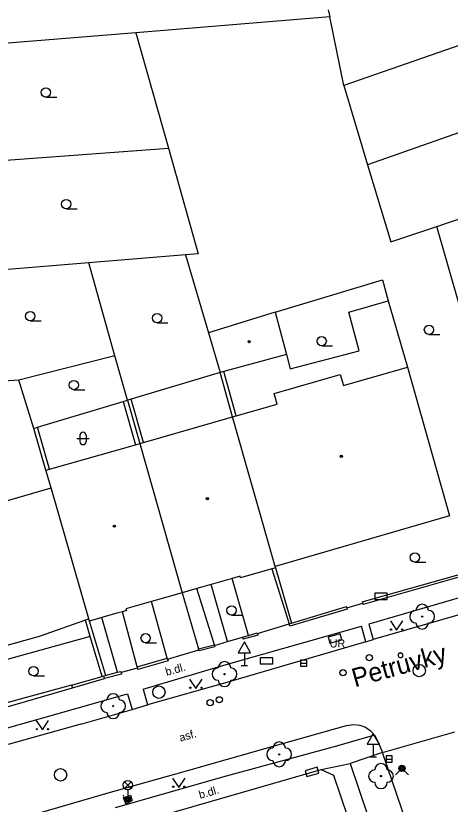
# Model space of a CAD drawing. Extents: x -596229 to -595156, y -1161237 to -1159376.
# Drawn here: x -596056.2 to -596021.2, y -1161042.3 to -1160978.8 of the extents above; entities that cross this region are included whole.
import ezdxf

# ---------------------------------------------------------------- set-up
doc = ezdxf.new("R2010")
doc.units = 0
for name, color, linetype in [('DOP - budovy nerozlisene - VP', 7, 'Continuous'), ('DOP - kresba z DSPS bez souradnic', 7, 'Continuous'), ('DOP - rozhrani ploch obecne', 7, 'Continuous'), ('Level 22', 7, 'Continuous'), ('Level 24', 7, 'Continuous'), ('Level 27', 7, 'Continuous'), ('Level 28', 7, 'Continuous'), ('Level 31', 7, 'Continuous'), ('Level 33', 7, 'Continuous'), ('Level 34', 7, 'Continuous'), ('Level 36', 7, 'Continuous'), ('Level 39', 7, 'Continuous'), ('Nazvy ulic', 7, 'Continuous'), ('Specificka linie pasportu komunikaci', 7, 'Continuous'), ('TM - budovy zdene_ betonove - VP', 7, 'Continuous'), ('TM - chodniky - VP', 7, 'Continuous'), ('TM - komunikace - VP', 7, 'Continuous'), ('TM - letecke snimky - pomocna linie', 7, 'Continuous'), ('TM - plot drateny_ kovovy - VP', 7, 'Continuous'), ('TM - plot dreveny - VP', 7, 'Continuous'), ('TM - plot zdeny_ ohradni zed - VP', 7, 'Continuous'), ('TM - podezdivka plotu - VP', 7, 'Continuous'), ('TM - popis objektu', 7, 'Continuous'), ('TM - popis povrchu', 7, 'Continuous'), ('TM - rozhrani mezi zpev. plochami mezi sebou - VP', 7, 'Continuous'), ('TM - rozhrani ploch obecne - VP', 7, 'Continuous'), ('TM - vjezd na pozemek', 7, 'Continuous')]:
    doc.layers.add(name, color=color, linetype=linetype)

msp = doc.modelspace()

# ---------------------------------------------------------------- linework, layer by layer
at = {"layer": 'DOP - budovy nerozlisene - VP'}
for points in [[(-596035.29, -1161002.69), (-596040.65, -1161004.33)], [(-596035.29, -1161002.69), (-596034.39, -1161006.09)], [(-596040.65, -1161004.33), (-596039.72, -1161007.54)], [(-596034.39, -1161006.09), (-596039.43, -1161007.46)], [(-596039.43, -1161007.46), (-596039.72, -1161007.54)]]:
    msp.add_lwpolyline(points, dxfattribs=at)
at = {"layer": 'DOP - kresba z DSPS bez souradnic'}
for points in [[(-596038.42, -1161011.03), (-596039.43, -1161007.46)], [(-596047.51, -1161009.87), (-596046.53, -1161013.34)], [(-596045.89, -1161013.16), (-596046.87, -1161009.68)], [(-596053.44, -1161015.32), (-596054.41, -1161011.94)]]:
    msp.add_lwpolyline(points, dxfattribs=at)
at = {"layer": 'DOP - rozhrani ploch obecne'}
for points in [[(-596006.38, -1160976.28), (-596029.78, -1160984.44)], [(-596031.02, -1160978.36), (-596030.9, -1160978.92)], [(-596030.9, -1160978.92), (-596046.51, -1160980.19)], [(-596029.78, -1160984.44), (-596030.9, -1160978.92)], [(-596046.51, -1160980.19), (-596062.76, -1160981.52)], [(-596046.51, -1160980.19), (-596043.88, -1160989.49)], [(-596004.21, -1160982.51), (-596027.86, -1160990.81)], [(-596029.78, -1160984.44), (-596027.86, -1160990.81)], [(-596062.05, -1160990.82), (-596043.88, -1160989.49)], [(-596043.88, -1160989.49), (-596041.48, -1160997.97)], [(-596022.3, -1160995.78), (-596006.25, -1160990.3)], [(-596027.86, -1160990.81), (-596025.98, -1160997.03)], [(-596025.98, -1160997.03), (-596022.3, -1160995.78)], [(-596042.5, -1160998.05), (-596050.27, -1160998.71)], [(-596041.48, -1160997.97), (-596042.5, -1160998.05)], [(-596042.5, -1160998.05), (-596040.65, -1161004.33)], [(-596050.27, -1160998.71), (-596061.38, -1160999.63)], [(-596048.18, -1161006.18), (-596050.27, -1160998.71)], [(-596035.29, -1161002.69), (-596026.67, -1161000.08)], [(-596026.67, -1161000.08), (-596026.19, -1161001.76)], [(-596026.19, -1161001.76), (-596024.65, -1161007.1)], [(-596048.18, -1161006.18), (-596055.9, -1161008.14)], [(-596047.16, -1161009.77), (-596048.18, -1161006.18)], [(-596039.72, -1161007.54), (-596046.87, -1161009.68)], [(-596038.71, -1161011.11), (-596039.72, -1161007.54)], [(-596055.9, -1161008.14), (-596060.7, -1161008.48)], [(-596054.7, -1161012.03), (-596055.9, -1161008.14)], [(-596054.41, -1161011.94), (-596047.51, -1161009.87)], [(-596047.51, -1161009.87), (-596047.16, -1161009.77)], [(-596046.87, -1161009.68), (-596047.16, -1161009.77)], [(-596047.16, -1161009.77), (-596046.18, -1161013.24)], [(-596054.7, -1161012.03), (-596054.41, -1161011.94)], [(-596053.73, -1161015.4), (-596054.7, -1161012.03)]]:
    msp.add_lwpolyline(points, dxfattribs=at)
at = {"layer": 'Level 22'}
for centre in [(-596023.47, -1161027.18), (-596039.37, -1161031.8), (-596048.32, -1161034.38), (-596034.97, -1161038.26), (-596026.78, -1161040.01)]:
    msp.add_circle(centre, 0.05, dxfattribs=at)
for centre, start, end in [((-596023.47, -1161026.68), 0, 180), ((-596023.97, -1161027.18), 90, 270), ((-596022.97, -1161027.18), 270, 90), ((-596023.47, -1161027.68), 180, 0), ((-596039.37, -1161031.3), 0, 180), ((-596039.87, -1161031.8), 90, 270), ((-596038.87, -1161031.8), 270, 90), ((-596039.37, -1161032.3), 180, 0), ((-596048.32, -1161033.88), 0, 180), ((-596048.82, -1161034.38), 90, 270), ((-596047.82, -1161034.38), 270, 90), ((-596048.32, -1161034.88), 180, 0), ((-596034.97, -1161037.76), 0, 180), ((-596035.47, -1161038.26), 90, 270), ((-596034.47, -1161038.26), 270, 90), ((-596034.97, -1161038.76), 180, 0), ((-596026.78, -1161039.51), 0, 180), ((-596027.28, -1161040.01), 90, 270), ((-596026.28, -1161040.01), 270, 90), ((-596026.78, -1161040.51), 180, 0)]:
    msp.add_arc(centre, 0.5, start, end, dxfattribs=at)
at = {"layer": 'Level 24'}
for points in [[(-596027.278, -1161025.799), (-596026.278, -1161025.799), (-596026.278, -1161025.299), (-596027.278, -1161025.299)], [(-596030.067, -1161028.563), (-596031.029, -1161028.836), (-596030.893, -1161029.317), (-596029.931, -1161029.044)], [(-596036.488, -1161030.989), (-596035.488, -1161030.989), (-596035.488, -1161030.489), (-596036.488, -1161030.489)], [(-596031.911, -1161039.296), (-596032.872, -1161039.574), (-596032.733, -1161040.055), (-596031.772, -1161039.777)]]:
    msp.add_lwpolyline(points, close=True, dxfattribs=at)
at = {"layer": 'Level 27'}
for p, q in [((-596033.24, -1161030.92), (-596032.74, -1161030.92)), ((-596026.37, -1161038.64), (-596025.87, -1161038.64))]:
    msp.add_line(p, q, dxfattribs=at)
for points in [[(-596033.24, -1161031.17), (-596032.74, -1161031.17), (-596032.74, -1161030.67), (-596033.24, -1161030.67)], [(-596026.37, -1161038.89), (-596025.87, -1161038.89), (-596025.87, -1161038.39), (-596026.37, -1161038.39)]]:
    msp.add_lwpolyline(points, close=True, dxfattribs=at)
for centre in [(-596023.7, -1161031.52), (-596044.64, -1161033.26), (-596052.55, -1161039.91)]:
    msp.add_circle(centre, 0.5, dxfattribs=at)
at = {"layer": 'Level 28'}
for centre in [(-596027.72, -1161030.48), (-596029.84, -1161031.68), (-596040.52, -1161034.11), (-596039.78, -1161033.87)]:
    msp.add_circle(centre, 0.25, dxfattribs=at)
at = {"layer": 'Level 31'}
msp.add_lwpolyline([(-596025.62, -1161039.92), (-596025.09, -1161039.39), (-596024.56, -1161039.92)], dxfattribs=at)
for radius in [0.25, 0.18, 0.11]:
    msp.add_circle((-596025.09, -1161039.39), radius, dxfattribs=at)
at = {"layer": 'Level 33'}
for p, q in [((-596047.415, -1161041), (-596046.885, -1161040.47)), ((-596047.415, -1161040.47), (-596046.885, -1161041)), ((-596047.15, -1161041.11), (-596047.15, -1161041.86))]:
    msp.add_line(p, q, dxfattribs=at)
for centre, radius in [((-596047.15, -1161040.735), 0.375), ((-596047.15, -1161041.86), 0.2), ((-596047.15, -1161041.86), 0.145), ((-596047.15, -1161041.86), 0.0876)]:
    msp.add_circle(centre, radius, dxfattribs=at)
at = {"layer": 'Level 34'}
for p, q in [((-596037.77, -1161030.082), (-596037.77, -1161031.1)), ((-596038.02, -1161031.1), (-596037.52, -1161031.1)), ((-596027.4, -1161037.442), (-596027.4, -1161038.46)), ((-596027.65, -1161038.46), (-596027.15, -1161038.46))]:
    msp.add_line(p, q, dxfattribs=at)
for points in [[(-596038.27, -1161030.082), (-596037.27, -1161030.082), (-596037.77, -1161029.216)], [(-596027.9, -1161037.442), (-596026.9, -1161037.442), (-596027.4, -1161036.576)]]:
    msp.add_lwpolyline(points, close=True, dxfattribs=at)
at = {"layer": 'Level 36'}
for p, q in [((-596053.73, -1160985.375), (-596052.855, -1160985.375)), ((-596052.1, -1160994.355), (-596051.225, -1160994.355)), ((-596054.99, -1161003.375), (-596054.115, -1161003.375)), ((-596044.79, -1161003.525), (-596043.915, -1161003.525)), ((-596022.92, -1161004.465), (-596022.045, -1161004.465)), ((-596031.55, -1161005.385), (-596030.675, -1161005.385)), ((-596051.48, -1161008.915), (-596050.605, -1161008.915)), ((-596051.246, -1161012.836), (-596050.246, -1161012.836)), ((-596050.996, -1161012.586), (-596050.996, -1161013.086)), ((-596050.496, -1161012.586), (-596050.496, -1161013.086)), ((-596024.05, -1161022.795), (-596023.175, -1161022.795)), ((-596038.8, -1161027.055), (-596037.925, -1161027.055)), ((-596045.71, -1161029.285), (-596044.835, -1161029.285)), ((-596054.72, -1161031.945), (-596053.845, -1161031.945))]:
    msp.add_line(p, q, dxfattribs=at)
for points in [[(-596026.02, -1161027.52), (-596025.52, -1161028.27), (-596025.02, -1161027.52)], [(-596042.17, -1161032.2), (-596041.67, -1161032.95), (-596041.17, -1161032.2)], [(-596054.51, -1161035.53), (-596054.01, -1161036.28), (-596053.51, -1161035.53)], [(-596043.54, -1161040.17), (-596043.04, -1161040.92), (-596042.54, -1161040.17)]]:
    msp.add_lwpolyline(points, dxfattribs=at)
for centre, radius in [((-596053.73, -1160985), 0.375), ((-596052.1, -1160993.98), 0.375), ((-596054.99, -1161003), 0.375), ((-596044.79, -1161003.15), 0.375), ((-596022.92, -1161004.09), 0.375), ((-596031.55, -1161005.01), 0.375), ((-596051.48, -1161008.54), 0.375), ((-596024.05, -1161022.42), 0.375), ((-596038.8, -1161026.68), 0.375), ((-596025.97, -1161028.22), 0.05), ((-596025.071, -1161028.22), 0.05), ((-596045.71, -1161028.91), 0.375), ((-596054.72, -1161031.57), 0.375), ((-596042.12, -1161032.9), 0.05), ((-596041.221, -1161032.9), 0.05), ((-596054.46, -1161036.23), 0.05), ((-596053.561, -1161036.23), 0.05), ((-596043.49, -1161040.87), 0.05), ((-596042.591, -1161040.87), 0.05)]:
    msp.add_circle(centre, radius, dxfattribs=at)
for centre, start, end in [((-596050.746, -1161012.586), 0, 180), ((-596050.746, -1161013.086), 180, 0)]:
    msp.add_arc(centre, 0.25, start, end, dxfattribs=at)
at = {"layer": 'Level 39'}
for centre, radius in [((-596037.38, -1161005.06), 0.09), ((-596037.38, -1161005.06), 0.0398), ((-596029.97, -1161014.28), 0.09), ((-596029.97, -1161014.28), 0.0398), ((-596040.74, -1161017.68), 0.09), ((-596040.74, -1161017.68), 0.0398), ((-596048.22, -1161019.9), 0.09), ((-596048.22, -1161019.9), 0.0398)]:
    msp.add_circle(centre, radius, dxfattribs=at)
at = {"layer": 'Specificka linie pasportu komunikaci'}
msp.add_lwpolyline([(-596026.67, -1161038.12), (-596020.83, -1161036.44)], dxfattribs=at)
at = {"layer": 'TM - budovy zdene_ betonove - VP'}
for points in [[(-596029.8, -1161008.57), (-596024.65, -1161007.1)], [(-596024.65, -1161007.1), (-596021.26, -1161019.06)], [(-596035.38, -1161009.23), (-596030.05, -1161007.7)], [(-596030.05, -1161007.7), (-596029.8, -1161008.57)], [(-596035.14, -1161010.09), (-596035.38, -1161009.23)], [(-596038.42, -1161011.03), (-596035.14, -1161010.09)], [(-596045.89, -1161013.16), (-596038.71, -1161011.11)], [(-596038.71, -1161011.11), (-596038.42, -1161011.03)], [(-596035.29, -1161023.15), (-596038.71, -1161011.11)], [(-596046.18, -1161013.24), (-596045.89, -1161013.16)], [(-596053.44, -1161015.32), (-596046.53, -1161013.34)], [(-596046.53, -1161013.34), (-596046.18, -1161013.24)], [(-596046.18, -1161013.24), (-596042.78, -1161025.25)], [(-596053.73, -1161015.4), (-596053.44, -1161015.32)], [(-596053.32, -1161016.82), (-596053.73, -1161015.4)], [(-596061.36, -1161019.14), (-596053.32, -1161016.82)], [(-596050.28, -1161027.36), (-596053.32, -1161016.82)], [(-596021.26, -1161019.06), (-596035.29, -1161023.15)], [(-596035.26, -1161023.26), (-596035.55, -1161023.34)], [(-596035.29, -1161023.15), (-596035.26, -1161023.26)], [(-596038.11, -1161023.92), (-596038.76, -1161024.11)], [(-596038.07, -1161024.06), (-596038.11, -1161023.92)], [(-596035.55, -1161023.34), (-596038.07, -1161024.06)], [(-596040.45, -1161024.59), (-596041.58, -1161024.91)], [(-596038.76, -1161024.11), (-596040.45, -1161024.59)], [(-596041.58, -1161024.91), (-596042.78, -1161025.25)], [(-596042.78, -1161025.25), (-596045.25, -1161025.96)], [(-596045.25, -1161025.96), (-596047.29, -1161026.54)], [(-596047.58, -1161026.79), (-596048.02, -1161026.91), (-596049.23, -1161027.26)], [(-596047.25, -1161026.69), (-596047.58, -1161026.79)], [(-596047.29, -1161026.54), (-596047.25, -1161026.69)], [(-596050.56, -1161027.46), (-596054.27, -1161028.78), (-596060.73, -1161030.57)], [(-596050.28, -1161027.36), (-596050.56, -1161027.46)], [(-596050.23, -1161027.55), (-596050.28, -1161027.36)], [(-596049.23, -1161027.26), (-596050.23, -1161027.55)], [(-596048.41, -1161044.34), (-596031.58, -1161039.47)], [(-596031.58, -1161039.47), (-596030.6, -1161039.94)], [(-596030.6, -1161039.94), (-596029.48, -1161043.26)]]:
    msp.add_lwpolyline(points, dxfattribs=at)
at = {"layer": 'TM - chodniky - VP'}
for points in [[(-596019.46, -1161025.38), (-596027.75, -1161027.78)], [(-596045.92, -1161033.02), (-596039.41, -1161031.09), (-596028.34, -1161027.95)], [(-596027.99, -1161029.2), (-596028.34, -1161027.95)], [(-596027.75, -1161027.78), (-596027.4, -1161029.03)], [(-596050.17, -1161028.78), (-596060.37, -1161031.6), (-596061.01, -1161031.68)], [(-596051.32, -1161034.57), (-596047.16, -1161033.4)], [(-596047.16, -1161033.4), (-596046.8, -1161034.65)], [(-596045.92, -1161033.02), (-596045.56, -1161034.27)], [(-596057.19, -1161036.23), (-596051.32, -1161034.57)], [(-596027.29, -1161036.73), (-596030.37, -1161037.6), (-596039.23, -1161040.02), (-596048.17, -1161042.57)], [(-596026.67, -1161038.12), (-596029.27, -1161039.01)], [(-596029.27, -1161039.01), (-596027.84, -1161043.21), (-596023.02, -1161057.42)]]:
    msp.add_lwpolyline(points, dxfattribs=at)
at = {"layer": 'TM - komunikace - VP'}
for points in [[(-596019.1, -1161026.64), (-596027.4, -1161029.03)], [(-596027.99, -1161029.2), (-596027.4, -1161029.03)], [(-596027.99, -1161029.2), (-596039.09, -1161032.46), (-596045.56, -1161034.27)], [(-596050.91, -1161035.83), (-596046.8, -1161034.65)], [(-596046.8, -1161034.65), (-596045.56, -1161034.27)], [(-596050.91, -1161035.83), (-596056.78, -1161037.47)], [(-596048.72, -1161041.37), (-596042.43, -1161039.6), (-596035.83, -1161037.7), (-596029.54, -1161035.95), (-596028.99, -1161035.85), (-596028.48, -1161035.92), (-596028.03, -1161036.08), (-596027.64, -1161036.33), (-596027.29, -1161036.73)], [(-596027.29, -1161036.73), (-596027.03, -1161037.22), (-596026.67, -1161038.12)], [(-596015.39, -1161071.31), (-596018.72, -1161061.56), (-596021.26, -1161054.1), (-596022.77, -1161049.52), (-596026.67, -1161038.12)], [(-596054.88, -1161043.15), (-596048.72, -1161041.37)]]:
    msp.add_lwpolyline(points, dxfattribs=at)
at = {"layer": 'TM - letecke snimky - pomocna linie'}
for points in [[(-596034.39, -1161006.09), (-596034.08, -1161007.25), (-596028.54, -1161005.78), (-596029.36, -1161002.67), (-596026.19, -1161001.76)], [(-596039.12, -1161029.18), (-596040.45, -1161024.59)], [(-596037.44, -1161028.69), (-596038.76, -1161024.11)], [(-596040.18, -1161029.45), (-596041.58, -1161024.91)], [(-596043.97, -1161030.52), (-596045.25, -1161025.96)], [(-596046.4, -1161031.23), (-596047.58, -1161026.79)], [(-596047.97, -1161031.66), (-596049.23, -1161027.26)]]:
    msp.add_lwpolyline(points, dxfattribs=at)
at = {"layer": 'TM - plot drateny_ kovovy - VP'}
for points in [[(-596035.55, -1161023.34), (-596034.16, -1161027.75)], [(-596028.28, -1161025.99), (-596019.82, -1161023.59)], [(-596033.99, -1161027.7), (-596029.56, -1161026.37)], [(-596034.16, -1161027.75), (-596033.99, -1161027.7)], [(-596046.4, -1161031.23), (-596043.97, -1161030.52)], [(-596049.08, -1161031.95), (-596048.93, -1161031.91)], [(-596048.93, -1161031.91), (-596047.97, -1161031.66)], [(-596047.97, -1161031.66), (-596047.7, -1161031.59)]]:
    msp.add_lwpolyline(points, dxfattribs=at)
at = {"layer": 'TM - plot dreveny - VP'}
for points in [[(-596037.91, -1161028.82), (-596037.44, -1161028.69)], [(-596037.44, -1161028.69), (-596036.74, -1161028.49)], [(-596041.45, -1161029.77), (-596040.18, -1161029.45)]]:
    msp.add_lwpolyline(points, dxfattribs=at)
at = {"layer": 'TM - plot zdeny_ ohradni zed - VP'}
for points in [[(-596050.17, -1161028.78), (-596050.56, -1161027.46)], [(-596049.21, -1161031.99), (-596050.17, -1161028.78)], [(-596051.66, -1161032.69), (-596049.21, -1161031.99)], [(-596049.21, -1161031.99), (-596049.08, -1161031.95)], [(-596051.66, -1161032.69), (-596059.86, -1161034.91), (-596060.8, -1161035)]]:
    msp.add_lwpolyline(points, dxfattribs=at)
at = {"layer": 'TM - podezdivka plotu - VP'}
for points in [[(-596035.26, -1161023.26), (-596033.99, -1161027.7)], [(-596019.79, -1161023.69), (-596019.76, -1161023.79), (-596028.22, -1161026.19), (-596028.25, -1161026.09)], [(-596029.53, -1161026.48), (-596029.5, -1161026.57), (-596034.1, -1161027.95), (-596034.16, -1161027.75)], [(-596029.53, -1161026.48), (-596029.56, -1161026.37)], [(-596028.28, -1161025.99), (-596028.25, -1161026.09)], [(-596037.91, -1161028.82), (-596037.86, -1161028.99)], [(-596036.72, -1161028.54), (-596036.69, -1161028.66), (-596037.86, -1161028.99)], [(-596036.74, -1161028.49), (-596036.72, -1161028.54)], [(-596040.17, -1161029.5), (-596040.14, -1161029.62), (-596041.41, -1161029.94), (-596041.43, -1161029.86)], [(-596040.17, -1161029.5), (-596040.18, -1161029.45)], [(-596041.43, -1161029.86), (-596041.45, -1161029.77)], [(-596043.94, -1161030.61), (-596043.91, -1161030.73), (-596046.34, -1161031.44), (-596046.37, -1161031.32)], [(-596043.94, -1161030.61), (-596043.97, -1161030.52)], [(-596046.4, -1161031.23), (-596046.37, -1161031.32)], [(-596051.6, -1161032.9), (-596049.02, -1161032.16)], [(-596049.02, -1161032.16), (-596049.08, -1161031.95)], [(-596047.67, -1161031.68), (-596047.64, -1161031.8), (-596049.02, -1161032.16)], [(-596047.67, -1161031.68), (-596047.7, -1161031.59)], [(-596051.66, -1161032.69), (-596051.6, -1161032.9)], [(-596057.7, -1161034.69), (-596051.6, -1161032.9)]]:
    msp.add_lwpolyline(points, dxfattribs=at)
at = {"layer": 'TM - rozhrani mezi zpev. plochami mezi sebou - VP'}
msp.add_lwpolyline([(-596031.58, -1161039.47), (-596029.27, -1161039.01)], dxfattribs=at)
at = {"layer": 'TM - rozhrani ploch obecne - VP'}
for points in [[(-596016.1, -1161017.39), (-596022.3, -1160995.78)], [(-596042.78, -1161025.25), (-596041.45, -1161029.77)], [(-596048.95, -1161031.83), (-596050.23, -1161027.55)], [(-596048.93, -1161031.91), (-596048.95, -1161031.83)], [(-596047.31, -1161042.24), (-596047.5, -1161041.76), (-596046.92, -1161041.54), (-596046.8, -1161041.98)], [(-596047.31, -1161042.24), (-596046.8, -1161041.98)]]:
    msp.add_lwpolyline(points, dxfattribs=at)
at = {"layer": 'TM - vjezd na pozemek'}
for points in [[(-596029.53, -1161026.48), (-596028.25, -1161026.09)], [(-596036.72, -1161028.54), (-596034.16, -1161027.75)], [(-596039.12, -1161029.18), (-596037.91, -1161028.82)], [(-596040.17, -1161029.5), (-596039.12, -1161029.18)], [(-596043.94, -1161030.61), (-596041.43, -1161029.86)], [(-596046.37, -1161031.32), (-596047.67, -1161031.68)]]:
    msp.add_lwpolyline(points, dxfattribs=at)

# ---------------------------------------------------------------- texts
at = {"layer": 'Nazvy ulic'}
msp.add_text('Petrůvky', height=1.5, rotation=15.52515, dxfattribs=at).set_placement((-596028.886, -1161032.869))
at = {"layer": 'TM - popis objektu'}
msp.add_text('UR', height=0.65, dxfattribs=at).set_placement((-596030.91, -1161029.66))
at = {"layer": 'TM - popis povrchu'}
for s, rotation, p in [('b.dl.', 15.74631, (-596044.02, -1161031.95)), ('asf.', 16.06001, (-596042.91, -1161037.25)), ('b.dl.', 16.13856, (-596041.33, -1161041.85)), ('b.', 21.59529, (-596047.36, -1161042.2))]:
    msp.add_text(s, height=0.65, rotation=rotation, dxfattribs=at).set_placement(p)

doc.saveas('drawing.dxf')
